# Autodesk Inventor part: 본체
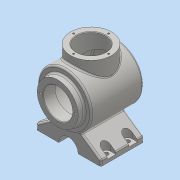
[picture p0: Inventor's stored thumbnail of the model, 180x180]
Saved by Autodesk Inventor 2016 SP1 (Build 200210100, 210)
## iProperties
Created: 2017-04
Part Number: 본체
Material: 일반
Document SubType Name: Modeling
Designer: CAMTIC
Density: 1 g/cm^3
Appearance: 기본값
Author: CAMTIC
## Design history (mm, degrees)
sketch "스케치1"
  geometry: L1 (-50, 50)-(46.336, 50); L2 (46.336, 50)-(46.336, 0); L3 (46.336, 0)-(-50, 0); L4 (-50, 0)-(-50, 50); L5 (-50, 0)-(-62, 0); L6 (-62, 0)-(-62, 38); L7 (-62, 38)-(-50, 38); L8 (-50, 38)-(-50, 0); L9 (0, 0)-(0, 50); L10 (46.336, 0)-(58, 0); A1 r 113 centre (-55, 0) between (58, 0) and (46.336, 50); 1 further point
  constraints: 20 end point, 4 parallel, 3 horizontal, 3 perpendicular, 3 point on line, 2 point on circle, 1 centre point, 1 coincident, 1 horizontal alignment
  dimensions: "d1" = 113 radius of A1; "d2" = 12 distance of L6.end L7.end; "d4" = 100 diameter of L1 L3; "d5" = 76 diameter of L7 L5; "d6" = 50 distance between parallel lines of L4 L9; "d8" = 108 distance from line of L4 L10.end
revolve "회전1" sketch "스케치1" stored, may be unused: angle "d9" = 90 deg
sketch "스케치2"
  geometry: C1 r 38 at (0, 0); 1 further point
  constraints: 1 centre point, 1 coincident
  dimensions: "d10" = 76 diameter of C1
extrude "돌출1" join sketch "스케치2" distance "d11" = 65; taper "d12" = 0 deg
node "작업 평면1"
sketch "스케치4"
  geometry: L1 (0, -29.988)-(-60, -72); L2 (-60, -72)-(-60, -82); L3 (-60, -82)-(60, -82); L4 (60, -82)-(60, -72); L5 (60, -72)-(0, -29.988); C1 r 18 at (0, -82); 1 further point
  constraints: 10 end point, 2 equal length, 2 perpendicular, 1 centre point, 1 midpoint, 1 vertical, 1 vertical alignment
  dimensions: "d16" = 55 deg angle of L2 L1; "d17" = 10 distance of L3.end L4.end; "d18" = 36 diameter of C1; "d19" = 120 distance of L2.end L3.end; "d20" = 82 distance from line of L3 point (0, 0)
extrude "돌출2" join sketch "스케치4" distance "d21" = 80; taper "d22" = 0 deg
extrude "돌출3" cut sketch "스케치4" stored distance "d23" = 80; taper "d24" = 0 deg
sketch "스케치5"
  geometry: L1 (-50, -50)-(46.336, -50) reference; L2 (-50, 50)-(46.336, 50) reference; L3 (-50, -50)-(-50, 50) reference; L4 (39.916, 40)-(-40, 40); L5 (-40, 40)-(-40, -40); L6 (-40, -40)-(39.916, -40); L7 (-40, 0)-(48, 0); L8 (-40, 27)-(-62, 27); L9 (-62, 27)-(-62, 0); L10 (-62, 0)-(-40, 0); L11 (-40, 0)-(-40, 27); A1 r 113 centre (-55, 0) between (46.336, -50) and (46.336, 50) reference; A2 r 103 centre (-55, 0) between (39.916, -40) and (39.916, 40); 1 further point
  constraints: 18 end point, 3 point on circle, 2 parallel, 1 centre point, 1 collinear, 1 horizontal, 1 midpoint, 1 perpendicular, 1 point on line, 2 other
  dimensions: "d25" = 10 radial gap between concentric circles of A1 A2; "d26" = 80 distance between parallel lines of L6 L4; "d27" = 22 distance between parallel lines of L5 L9; "d28" = 54 diameter of L8 L7
revolve "회전2" sketch "스케치5" stored, may be unused: angle "d29" = 90 deg
hole "구멍1" diameter "d32" = 54; stored, may be unused: countersink angle "d36" = 90 deg, drill point angle "d38" = 0 deg; dims "d33" = 6, "d34" = 4, "d35" = 2, "d37" = 8, "d41" = 10, "d42" = 10
node "작업 평면2"
sketch "스케치6"
  geometry: L1 (-50, -22)-(-60, -22); L2 (-50, -14)-(-60, -14); L3 (-60, -30)-(-50, -30); L4 (-95.2, 0)-(95.2, 0) reference; L5 (0, -86)-(0, 82) reference; L6 (-60, -42)-(-60, 38) reference; L7 (-21.584, -42)-(-60, -42) reference; L8 (60, -30)-(50, -30); L9 (50, -14)-(60, -14); L10 (50, -22)-(60, -22); L11 (-50, 18)-(-60, 18); L12 (-50, 26)-(-60, 26); L13 (-60, 10)-(-50, 10); L14 (50, 26)-(60, 26); L15 (60, 10)-(50, 10); L16 (50, 18)-(60, 18); A1 r 8 centre (-50, -22) between (-50, -30) and (-50, -14); A2 r 8 centre (-60, -22) between (-60, -14) and (-60, -30); A3 r 8 centre (60, -22) between (60, -30) and (60, -14); A4 r 8 centre (50, -22) between (50, -14) and (50, -30); A5 r 8 centre (-50, 18) between (-50, 10) and (-50, 26); A6 r 8 centre (-60, 18) between (-60, 26) and (-60, 10); A7 r 8 centre (60, 18) between (60, 10) and (60, 26); A8 r 8 centre (50, 18) between (50, 26) and (50, 10); 4 further points
  constraints: 32 end point, 16 point on circle, 13 symmetric about line, 8 centre point, 8 tangent, 3 parallel, 2 horizontal, 2 midpoint, 2 point on line, 1 equal radius, 4 other
  dimensions: "d40" = 8 radius of A1; "d43" = 10 distance from line of L1.start L6; "d44" = 20 distance from line of L7 L1.end; "d114" = 40 distance of L1.end L11.end
extrude "돌출4" cut sketch "스케치6" distance "d45" = 20; taper "d46" = 0 deg
hole "구멍2" diameter "d49" = 8; stored, may be unused: countersink angle "d53" = 90 deg, drill point angle "d55" = 118 deg; dims "d47" = 10, "d48" = 10, "d50" = 6, "d51" = 4, "d52" = 2, "d54" = 8
hole "구멍3" diameter "d58" = 8; stored, may be unused: countersink angle "d62" = 90 deg, drill point angle "d64" = 118 deg; dims "d59" = 6, "d60" = 4, "d61" = 2, "d63" = 8, "d115" = 10, "d116" = 10
hole "구멍4" diameter "d67" = 8; stored, may be unused: countersink angle "d71" = 90 deg, drill point angle "d73" = 118 deg; dims "d65" = 10, "d66" = 10, "d68" = 6, "d69" = 4, "d70" = 2, "d72" = 8
hole "구멍5" diameter "d76" = 8; stored, may be unused: countersink angle "d80" = 90 deg, drill point angle "d82" = 118 deg; dims "d77" = 6, "d78" = 4, "d79" = 2, "d81" = 8, "d117" = 10, "d118" = 10
sketch "스케치8"
  geometry: 2 further points
  constraints: 1 vertical alignment
  dimensions: "d83" = 32.5 distance of point (0, 0) point (0, 32.5)
hole "구멍6" sketch "스케치8" at (0, 32.5) diameter "d84" = 3.242; stored, may be unused: countersink angle "d88" = 90 deg, drill point angle "d90" = 118 deg; dims "d85" = 8, "d86" = 4, "d87" = 2, "d89" = 10
sketch "스케치9"
  geometry: 2 further points
  constraints: 1 horizontal alignment
  dimensions: "d94" = 32.5 distance of point (0, 0) point (-32.5, 0)
hole "구멍7" sketch "스케치9" at (-32.5, 0) diameter "d95" = 3.242; stored, may be unused: countersink angle "d99" = 90 deg, drill point angle "d101" = 118 deg; dims "d96" = 8, "d97" = 4, "d98" = 2, "d100" = 10
fillet "모깎기1" dims "d105" = 3
chamfer "모따기1" distance "d106" = 1; stored, may be unused: second distance "d107" = 2, angle "d108" = 45 deg
fillet "모깎기2" dims "d109" = 3
fillet "모깎기3" dims "d110" = 3
fillet "모깎기4" dims "d111" = 3
fillet "모깎기5" dims "d112" = 3
fillet "모깎기6" dims "d113" = 3
node "솔리드1"
pattern_circular "원형 패턴1" dims angle "d92" = 360 deg
pattern_circular "원형 패턴2" dims angle "d103" = 360 deg
other parameters: "d15" = -8, "d39" = -76
